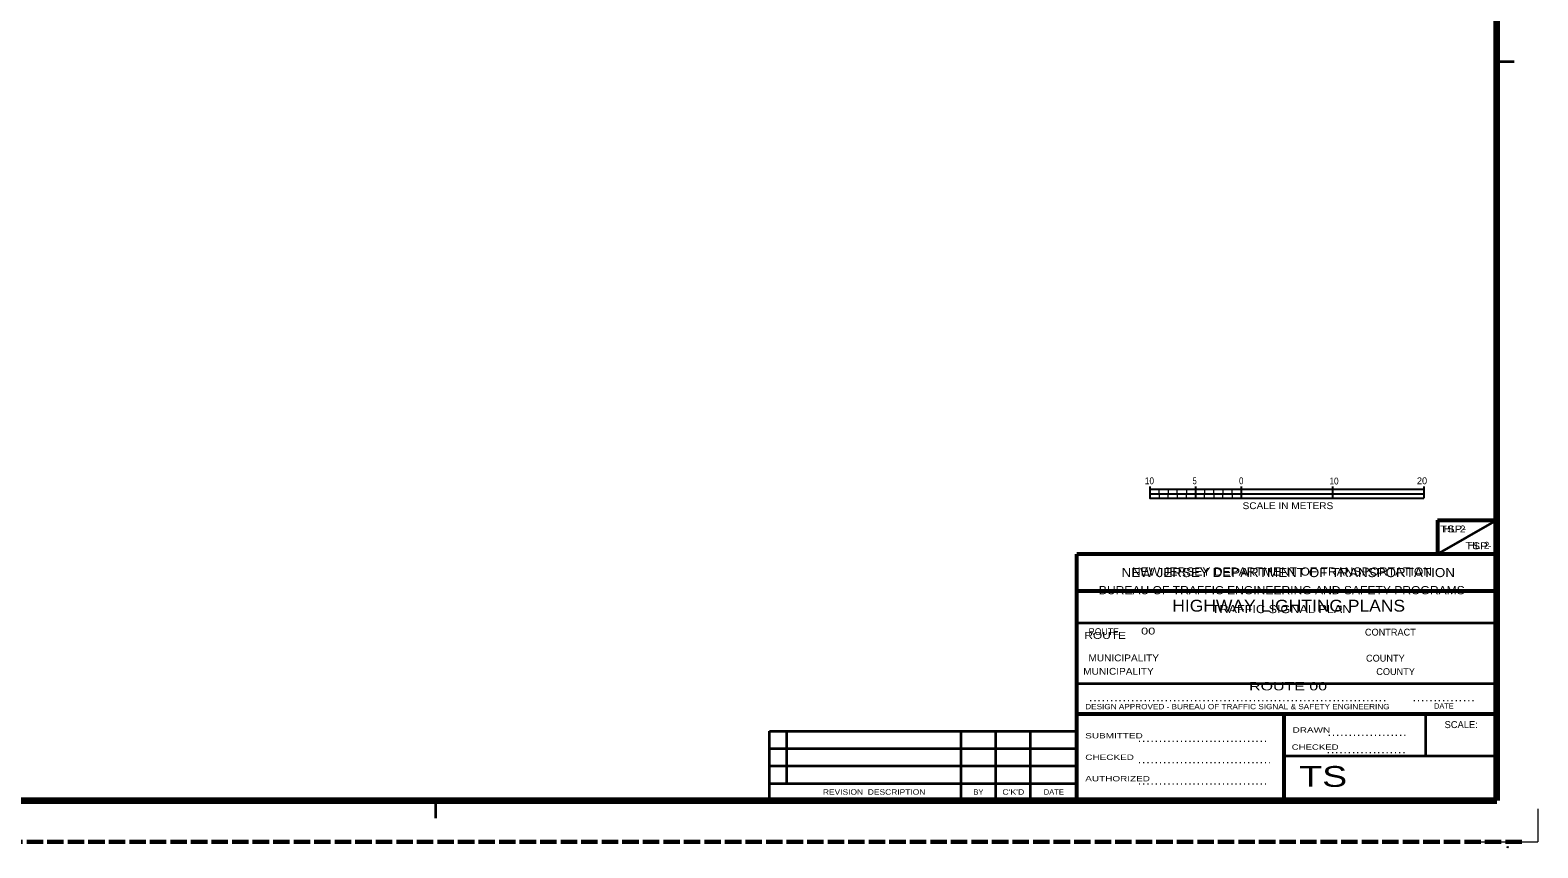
# Model space of a CAD drawing. Extents: x 168423 to 169398, y 223542 to 223937.
# Drawn here: x 169232.6 to 169397.8, y 223542 to 223631.6 of the extents above; entities that cross this region are included whole.
import ezdxf
from ezdxf.enums import TextEntityAlignment as Align

# ---------------------------------------------------------------- set-up
doc = ezdxf.new("R2010")
doc.units = 0
doc.header["$LTSCALE"] = 0.3
doc.header["$PDMODE"] = 32
doc.header["$PDSIZE"] = 0.15
doc.linetypes.add('DOTTED', pattern=[1.5, 0.3, -1.2])
doc.linetypes.add('LONG_DASHED', pattern=[7.5, 6, -1.5])
for name, color, linetype, lineweight in [('1', 7, 'Continuous', 13), ('25', 7, 'Continuous', 35), ('27', 7, 'Continuous', 35), ('38', 7, 'Continuous', 53), ('63', 7, 'Continuous', 53)]:
    doc.layers.add(name, color=color, linetype=linetype, lineweight=lineweight)
doc.layers.add('12', color=7, linetype='Continuous')

msp = doc.modelspace()

# ---------------------------------------------------------------- linework, layer by layer
at = {"layer": '1', "lineweight": 35}
for p, q in [((169393.3094, 223628.1285), (169395.2294, 223628.1285)), ((169277.0594, 223547.1285), (169277.0594, 223545.2085))]:
    msp.add_line(p, q, dxfattribs=at)
at = {"layer": '1', "lineweight": 25}
for p, q in [((169360.3094, 223581.5667), (169360.3094, 223580.2692)), ((169365.3094, 223581.5667), (169365.3094, 223580.2692)), ((169375.3094, 223581.5667), (169375.3094, 223580.2692)), ((169385.3094, 223581.5667), (169385.3094, 223580.2692)), ((169355.3094, 223581.2692), (169385.3094, 223581.2692)), ((169355.3094, 223580.7692), (169385.3094, 223580.7692)), ((169357.1494, 223581.2692), (169358.1694, 223581.2692)), ((169359.1894, 223581.2692), (169360.2094, 223581.2692)), ((169361.2294, 223581.2692), (169362.2494, 223581.2692)), ((169363.2694, 223581.2692), (169364.2894, 223581.2692))]:
    msp.add_line(p, q, dxfattribs=at)
at = {"layer": '1'}
for p in [(169397.8094, 223546.2285), (169390.9094, 223542.6285)]:
    msp.add_line(p, (169397.8094, 223542.6285), dxfattribs=at)
at = {"layer": '1', "linetype": 'LONG_DASHED', "lineweight": 60}
msp.add_line((169396.0594, 223542.6285), (169127.8354, 223542.6285), dxfattribs=at)
at = {"layer": '1', "lineweight": 158}
msp.add_lwpolyline([(169393.3094, 223547.1285), (169393.3094, 223709.1285), (169160.8094, 223709.1285), (169160.8094, 223547.1285)], close=True, dxfattribs=at)
at = {"layer": '1', "lineweight": 25}
msp.add_lwpolyline([(169355.3094, 223581.5667), (169355.3094, 223580.2692), (169385.3094, 223580.2692)], dxfattribs=at)
at = {"layer": '1'}
for points in [[(169355.3094, 223580.7692), (169356.3094, 223580.7692), (169356.3094, 223581.2692), (169355.3094, 223581.2692)], [(169356.3094, 223580.2692), (169357.3094, 223580.2692), (169357.3094, 223580.7692), (169356.3094, 223580.7692)], [(169357.3094, 223580.7692), (169358.3094, 223580.7692), (169358.3094, 223581.2692), (169357.3094, 223581.2692)], [(169358.3094, 223580.2692), (169359.3094, 223580.2692), (169359.3094, 223580.7692), (169358.3094, 223580.7692)], [(169359.3094, 223580.7692), (169360.3094, 223580.7692), (169360.3094, 223581.2692), (169359.3094, 223581.2692)], [(169360.3094, 223580.2692), (169361.3094, 223580.2692), (169361.3094, 223580.7692), (169360.3094, 223580.7692)], [(169361.3094, 223580.7692), (169362.3094, 223580.7692), (169362.3094, 223581.2692), (169361.3094, 223581.2692)], [(169362.3094, 223580.2692), (169363.3094, 223580.2692), (169363.3094, 223580.7692), (169362.3094, 223580.7692)], [(169363.3094, 223580.7692), (169364.3094, 223580.7692), (169364.3094, 223581.2692), (169363.3094, 223581.2692)], [(169364.3094, 223580.2692), (169365.3094, 223580.2692), (169365.3094, 223580.7692), (169364.3094, 223580.7692)], [(169365.3094, 223580.7692), (169375.3094, 223580.7692), (169375.3094, 223581.2692), (169365.3094, 223581.2692)], [(169375.3094, 223580.2692), (169385.3094, 223580.2692), (169385.3094, 223580.7692), (169375.3094, 223580.7692)]]:
    msp.add_lwpolyline(points, close=True, dxfattribs=at)
msp.add_point((169394.5094, 223542.0285), dxfattribs=at)
at = {"layer": '25'}
msp.add_line((169386.8094, 223574.1285), (169393.3094, 223577.8785), dxfattribs=at)
at = {"layer": '25', "lineweight": 53}
for p, q in [((169386.8094, 223577.8785), (169393.3094, 223577.8785)), ((169386.8094, 223577.8785), (169386.8094, 223574.1285)), ((169347.3094, 223547.1285), (169347.3094, 223574.1285)), ((169393.3094, 223574.1285), (169347.3094, 223574.1285)), ((169347.3094, 223570.1285), (169393.3094, 223570.1285))]:
    msp.add_line(p, q, dxfattribs=at)
at = {"layer": '27', "lineweight": 53}
for p in [(169347.3094, 223547.1285), (169393.3094, 223574.1285)]:
    msp.add_line(p, (169347.3094, 223574.1285), dxfattribs=at)
at = {"layer": '27'}
for p, q in [((169393.3094, 223566.5985), (169347.3094, 223566.5985)), ((169393.3094, 223559.9385), (169347.3094, 223559.9385)), ((169393.3094, 223556.6085), (169347.3094, 223556.6085)), ((169369.9694, 223547.1285), (169369.9694, 223556.6085)), ((169385.5394, 223552.0185), (169385.5394, 223556.6085)), ((169313.6194, 223554.7485), (169347.3094, 223554.7485)), ((169313.6194, 223547.1285), (169313.6194, 223554.7485)), ((169315.5394, 223549.0185), (169315.5394, 223554.7485)), ((169334.6194, 223547.1285), (169334.6194, 223554.7485)), ((169338.4294, 223547.1285), (169338.4294, 223554.7485)), ((169342.2394, 223547.1285), (169342.2394, 223554.7485)), ((169313.6194, 223552.8585), (169347.3094, 223552.8585)), ((169393.3094, 223552.0185), (169369.9694, 223552.0185)), ((169313.6194, 223550.9385), (169347.3094, 223550.9385)), ((169313.6194, 223549.0185), (169347.3094, 223549.0185))]:
    msp.add_line(p, q, dxfattribs=at)
at = {"layer": '27', "linetype": 'DOTTED', "lineweight": 13}
for p, q in [((169348.7742, 223558.1187), (169381.1543, 223558.1187)), ((169384.2204, 223558.1187), (169390.8074, 223558.1187)), ((169354.1239, 223553.6607), (169368.3806, 223553.6607)), ((169354.1239, 223553.6607), (169368.3806, 223553.6607)), ((169374.9097, 223554.2938), (169383.3891, 223554.2938)), ((169374.8096, 223552.4196), (169383.2891, 223552.4196)), ((169354.1239, 223551.3043), (169368.4261, 223551.3043)), ((169354.1239, 223551.3043), (169368.4261, 223551.3043)), ((169354.1239, 223548.957), (169368.3806, 223548.957))]:
    msp.add_line(p, q, dxfattribs=at)
at = {"layer": '38', "lineweight": 35}
msp.add_line((169386.8094, 223574.1285), (169393.3094, 223577.8785), dxfattribs=at)
at = {"layer": '38'}
for q in [(169393.3094, 223577.8785), (169386.8094, 223574.1285)]:
    msp.add_line((169386.8094, 223577.8785), q, dxfattribs=at)
at = {"layer": '63'}
for p, q in [((169393.3094, 223556.6085), (169347.3094, 223556.6085)), ((169369.9694, 223556.6085), (169369.9694, 223547.1285))]:
    msp.add_line(p, q, dxfattribs=at)

# ---------------------------------------------------------------- texts
at = {"layer": '1'}
for s, width, p in [('10', 0.9, (169355.2602, 223581.8092)), ('5', 0.75, (169360.212, 223581.8092)), ('0', 0.85, (169365.3145, 223581.8092)), ('10', 0.9, (169375.4803, 223581.7792)), ('SCALE IN METERS', 1.1, (169370.4308, 223579.0792))]:
    msp.add_text(s, height=0.7501, dxfattribs=dict(at, width=width)).set_placement(p, align=Align.CENTER)
msp.add_text('20', height=0.7501, dxfattribs=at).set_placement((169385.1211, 223581.8092), align=Align.CENTER)
at = {"layer": '12', "width": 1.1}
for s, height, p in [('HL-2', 0.75, (169388.6866, 223576.5325)), ('HL-2', 0.75, (169391.3059, 223574.7431)), ('HIGHWAY LIGHTING PLANS', 1.3, (169370.514, 223567.8452))]:
    msp.add_text(s, height=height, dxfattribs=at).set_placement(p, align=Align.CENTER)
at = {"layer": '25'}
for s, height, width, p in [('NEW JERSEY DEPARTMENT OF TRANSPORTATION', 1, 1.1, (169370.4669, 223571.6285)), ('                   ROUTE 00                  ', 0.9, 1.45, (169370.2071, 223559.2185))]:
    msp.add_text(s, height=height, dxfattribs=dict(at, width=width)).set_placement(p, align=Align.CENTER)
for s, width, p in [('ROUTE', 0.95, (169348.5794, 223565.2785)), ('00                        ', 1.4, (169354.3394, 223565.3385)), ('MUNICIPALITY', 1.1, (169348.5794, 223562.3985))]:
    msp.add_text(s, height=0.75, dxfattribs=dict(at, width=width)).set_placement(p)
for s, p in [('CONTRACT', (169378.8669, 223565.2185)), ('COUNTY', (169378.9869, 223562.3685))]:
    msp.add_text(s, height=0.75, dxfattribs=at).set_placement(p)
at = {"layer": '27'}
for s, height, width, p in [('NEW JERSEY DEPARTMENT OF TRANSPORTATION', 0.9, 1.1, (169369.7778, 223571.7885)), ('BUREAU OF TRAFFIC ENGINEERING AND SAFETY PROGRAMS', 0.9, 1.1, (169369.76, 223569.7485)), ('TRAFFIC SIGNAL PLAN', 0.9, 1.15, (169369.7355, 223567.6785)), ('REVISION  DESCRIPTION', 0.6, 1.15, (169325.0982, 223547.7765)), ('BY', 0.6, 0.9, (169336.5272, 223547.7765)), ("C'K'D", 0.6, 1.2, (169340.3512, 223547.7765))]:
    msp.add_text(s, height=height, dxfattribs=dict(at, width=width)).set_placement(p, align=Align.CENTER)
for s, height, width, p in [('ROUTE                                                         ', 0.75, 1.3, (169348.1294, 223564.8585)), ('MUNICIPALITY', 0.75, 1.1, (169348.0094, 223560.9285)), ('DESIGN APPROVED - BUREAU OF TRAFFIC SIGNAL & SAFETY ENGINEERING', 0.5823, 1.15, (169348.2283, 223557.1452)), ('DRAWN                     ', 0.5822, 1.4, (169370.9429, 223554.585)), ('SUBMITTED                        ', 0.5823, 1.4, (169348.2283, 223553.9518)), ('CHECKED                          ', 0.5823, 1.4, (169348.2283, 223551.5954)), ('CHECKED                  ', 0.5822, 1.35, (169370.8429, 223552.7108)), ('TS     ', 2.275, 1.35, (169371.6708, 223548.6431)), ('AUTHORIZED                       ', 0.5823, 1.4, (169348.2283, 223549.2481))]:
    msp.add_text(s, height=height, dxfattribs=dict(at, width=width)).set_placement(p)
msp.add_text('COUNTY', height=0.75, dxfattribs=at).set_placement((169380.109, 223560.8985))
for s, height, p in [('DATE', 0.5823, (169387.5174, 223557.2089)), ('SCALE:', 0.7642, (169389.4109, 223555.08)), ('DATE', 0.6, (169344.7827, 223547.7765))]:
    msp.add_text(s, height=height, dxfattribs=at).set_placement(p, align=Align.CENTER)
at = {"layer": '38', "width": 1.25}
for p in [(169388.6866, 223576.5325), (169391.4826, 223574.6825)]:
    msp.add_text('TSP- ', height=0.75, dxfattribs=at).set_placement(p, align=Align.CENTER)

doc.saveas('drawing.dxf')
